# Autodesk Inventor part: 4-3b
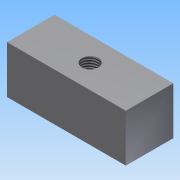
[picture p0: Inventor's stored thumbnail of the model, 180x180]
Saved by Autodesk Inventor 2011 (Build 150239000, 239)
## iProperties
Created: 2014-03
Part Number: 4-3b
Document SubType Name: Modeling
Designer: Administrator
Density: 1 g/cm^3
Author: Administrator
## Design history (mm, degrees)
sketch "草图1"
  geometry: L1 (-50, 20)-(50, 20); L2 (50, 20)-(50, -20); L3 (50, -20)-(-50, -20); L4 (-50, -20)-(-50, 20); 3 further points
  constraints: 8 end point, 2 midpoint, 2 parallel, 1 horizontal, 1 horizontal alignment, 1 perpendicular, 1 vertical alignment
  dimensions: "d0" = 100 distance of L2.end L3.end; "d1" = 40 distance of L3.end L1.start
extrude "拉伸1" new body sketch "草图1" distance "d2" = 40; taper "d3" = 0 deg
hole "Hole1" diameter "d6" = 13.835; stored, may be unused: countersink angle "d10" = 90 deg, drill point angle "d12" = 120 deg; dims "d4" = 20, "d5" = 50, "d7" = 24, "d8" = 4, "d9" = 2, "d11" = 32
node "实体1"
